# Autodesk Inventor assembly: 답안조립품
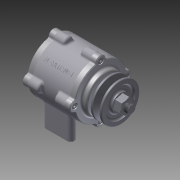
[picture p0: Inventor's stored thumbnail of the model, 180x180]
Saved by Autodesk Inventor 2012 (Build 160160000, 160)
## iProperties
Created: 2015-03
Part Number: 답안조립품
Document SubType Name: Assembly
Designer: Owner
Author: Owner
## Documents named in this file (11)
- C:\Documents and Settings\Owner\바탕 화면\450305V1001\답안조립품.iam
- C:\Documents and Settings\Owner\바탕 화면\450305V1001\본체.ipt
- C:\Documents and Settings\Owner\바탕 화면\450305V1001\베어링 6204.ipt
- C:\Documents and Settings\Owner\바탕 화면\450305V1001\커버.ipt
- C:\Documents and Settings\Owner\바탕 화면\450305V1001\커버2.ipt
- C:\Documents and Settings\Owner\바탕 화면\450305V1001\M 4 x 12.ipt
- C:\Documents and Settings\Owner\바탕 화면\450305V1001\축.ipt
- C:\Documents and Settings\Owner\바탕 화면\450305V1001\오일실.ipt
- C:\Documents and Settings\Owner\바탕 화면\450305V1001\키(4 x 4 x 12).ipt
- C:\Documents and Settings\Owner\바탕 화면\450305V1001\V벨트풀리.ipt
- C:\Documents and Settings\Owner\바탕 화면\450305V1001\너트 M12x1.25.ipt
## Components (14 placed, 6 different names)
1. KS B 2023 6204 - 20 x 47 x 14:1
2. KS B 2023 6204 - 20 x 47 x 14:2
3. KS B 2804 D D - 20 32 8:1
4. KS B 1311 (I) 4 x 4 x 12:1 — 각도:1, 각도:2
5. 그루브 풀리1:1 — 각도:2
6. KS B 1012 클래스 1 일반 - 미터 M12x1.25:1
7. KS B 1003 - 미터 M 4 x 12:1
8. KS B 1003 - 미터 M 4 x 12:2
9. KS B 1003 - 미터 M 4 x 12:3
10. KS B 1003 - 미터 M 4 x 12:4
11. KS B 1003 - 미터 M 4 x 12:5
12. KS B 1003 - 미터 M 4 x 12:6
13. KS B 1003 - 미터 M 4 x 12:7
14. KS B 1003 - 미터 M 4 x 12:8
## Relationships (2: Angle 2)
- 각도:1 [Angle]: KS B 1311 (I) 4 x 4 x 12:1
- 각도:2 [Angle]: KS B 1311 (I) 4 x 4 x 12:1 ↔ 그루브 풀리1:1
